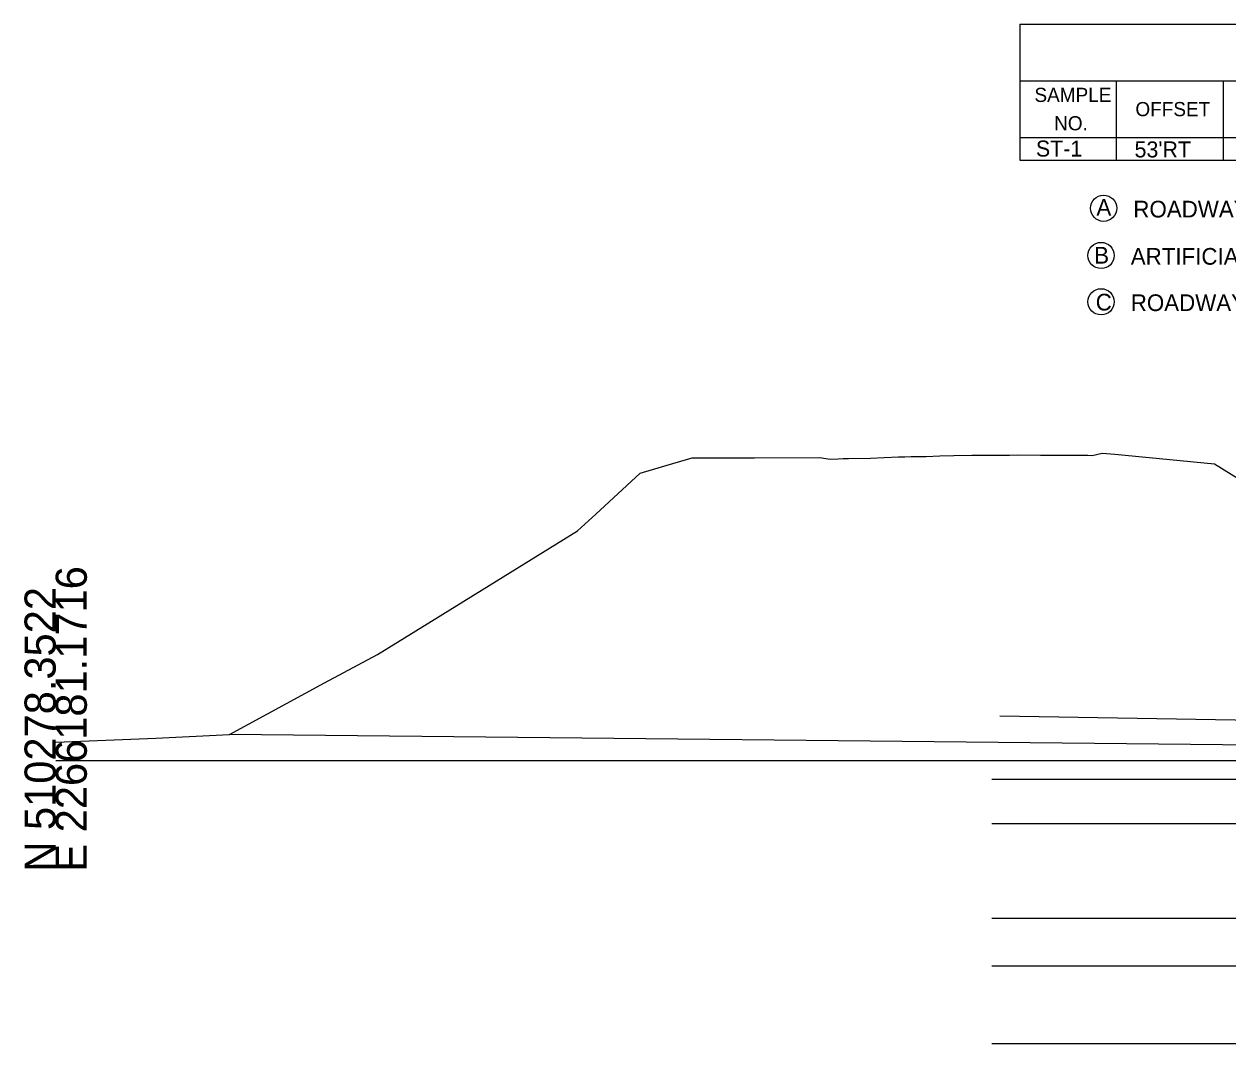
# Model space of a CAD drawing. Extents: x -827 to 2303, y -169 to 9934.
# Drawn here: x -2.8 to 105.4, y 8974.5 to 9066.3 of the extents above; entities that cross this region are included whole.
import ezdxf

# ---------------------------------------------------------------- set-up
doc = ezdxf.new("R2010")
doc.units = 0
for name, color, linetype in [('Default', 7, 'Continuous'), ('Exist Cross Section Cell', 7, 'Continuous'), ('Exist XS Ground Line', 7, 'Continuous'), ('Geotech Sheets and Borders Cell', 7, 'Continuous'), ('Prop DirtTable_ Soil Test Results - Tx (Sample Data)', 7, 'Continuous'), ('Prop Road Sect_ Material - Bubble + Leader + Bubble Tx', 7, 'Continuous'), ('Prop Road Sect_ Material - Contact (General - Major)', 7, 'Continuous'), ('Prop Road Sect_ Material - Contact (General - Minor)', 7, 'Continuous'), ('Prop Road Sect_ Material - Tx (Composite Desc)', 7, 'Continuous')]:
    doc.layers.add(name, color=color, linetype=linetype)

msp = doc.modelspace()

# ---------------------------------------------------------------- linework, layer by layer
at = {"layer": 'Exist Cross Section Cell'}
msp.add_line((0, 9000), (150, 9000), dxfattribs=at)
at = {"layer": 'Exist XS Ground Line'}
msp.add_lwpolyline([(0, 9001.65), (9.02, 9002.02), (15.64, 9002.35), (24.16, 9006.98), (28.93, 9009.53), (34.8, 9013.17), (46.92, 9020.66), (48.56, 9022.16), (52.56, 9025.85), (54.47, 9026.43), (57.23, 9027.22), (62.85, 9027.24), (68.71, 9027.25), (69.26, 9027.17), (69.66, 9027.1), (70.35, 9027.14), (70.82, 9027.16), (71.3, 9027.17), (73.28, 9027.2), (74.5, 9027.26), (75.78, 9027.32), (76.35, 9027.33), (76.91, 9027.35), (77.73, 9027.36), (78.28, 9027.36), (79.49, 9027.41), (80.77, 9027.45), (82.37, 9027.46), (83.28, 9027.46), (83.79, 9027.46), (84.14, 9027.46), (85.77, 9027.48), (86.47, 9027.49), (88.55, 9027.48), (89.68, 9027.47), (90.85, 9027.48), (92.8, 9027.48), (93.2, 9027.45), (94.11, 9027.66), (95.23, 9027.56), (104.2, 9026.7), (107.21, 9024.83)], dxfattribs=at)
at = {"layer": 'Geotech Sheets and Borders Cell'}
for p, q in [((86.69, 9066.26), (86.69, 9056.06)), ((86.69, 9066.26), (214.48, 9066.26)), ((86.69, 9061.16), (214.48, 9061.16)), ((95.36, 9061.16), (95.36, 9054)), ((104.98, 9061.16), (104.98, 9054)), ((86.69, 9056.06), (214.48, 9056.06)), ((86.69, 9056.06), (214.48, 9056.06)), ((86.69, 9056.06), (86.69, 9054)), ((86.69, 9054), (214.48, 9054)), ((86.69, 9054), (214.48, 9054))]:
    msp.add_line(p, q, dxfattribs=at)
at = {"layer": 'Prop Road Sect_ Material - Bubble + Leader + Bubble Tx'}
for centre in [(94.23, 9049.69), (94, 9045.44), (94, 9041.27)]:
    msp.add_circle(centre, 1.18, dxfattribs=at)
at = {"layer": 'Prop Road Sect_ Material - Contact (General - Major)'}
msp.add_line((202, 9000.4), (15.64, 9002.35), dxfattribs=at)
at = {"layer": 'Prop Road Sect_ Material - Contact (General - Minor)'}
for p, q in [((202, 9002), (84.9, 9003.98)), ((197.81, 8998.3), (84.18, 8998.3)), ((197.44, 8994.3), (84.18, 8994.3)), ((202, 8985.8), (84.18, 8985.8)), ((202, 8981.5), (84.18, 8981.5)), ((197.5, 8974.5), (84.18, 8974.5))]:
    msp.add_line(p, q, dxfattribs=at)

# ---------------------------------------------------------------- texts
at = {"layer": 'Default'}
msp.add_text('-', height=0.0001, dxfattribs=at).set_placement((0, 9000))
msp.add_text('-', height=0.0001, dxfattribs=at).set_placement((0, 9000))
at = {"layer": 'Exist Cross Section Cell'}
for s, p in [('E 2266181.1716', (2.8, 8990)), ('N 510278.3522', (0, 8990))]:
    msp.add_text(s, height=2.8, rotation=90, dxfattribs=at).set_placement(p)
at = {"layer": 'Geotech Sheets and Borders Cell'}
for s, p in [('SAMPLE', (88.01, 9059.25)), ('OFFSET', (97.09, 9057.97)), ('NO.', (89.78, 9056.7))]:
    msp.add_text(s, height=1.275, dxfattribs=at).set_placement(p)
at = {"layer": 'Prop DirtTable_ Soil Test Results - Tx (Sample Data)'}
for s, p in [('ST-1', (88.14, 9054.34)), ("53'RT", (97.01, 9054.26))]:
    msp.add_text(s, height=1.44, dxfattribs=at).set_placement(p)
at = {"layer": 'Prop Road Sect_ Material - Tx (Composite Desc)'}
for s, p in [('A', (93.58, 9049.02)), ('ROADWAY EMBANKMENT: Orange-Brown and Dark-Gray, Stiff, Clayey SILT (A-5), Moist (Old Roadway Subgrade)', (96.9, 9048.86)), ('B', (93.38, 9044.71)), ('ARTIFICIAL FILL: Orange-Brown, Loose, Silty SAND (A-2-4), Moist, ', (96.67, 9044.61)), ('C', (93.52, 9040.49)), ('ROADWAY EMBANKMENT: ASPHALT Over CONCRETE (Old Road)', (96.67, 9040.44))]:
    msp.add_text(s, height=1.5, dxfattribs=at).set_placement(p)

doc.saveas('drawing.dxf')
